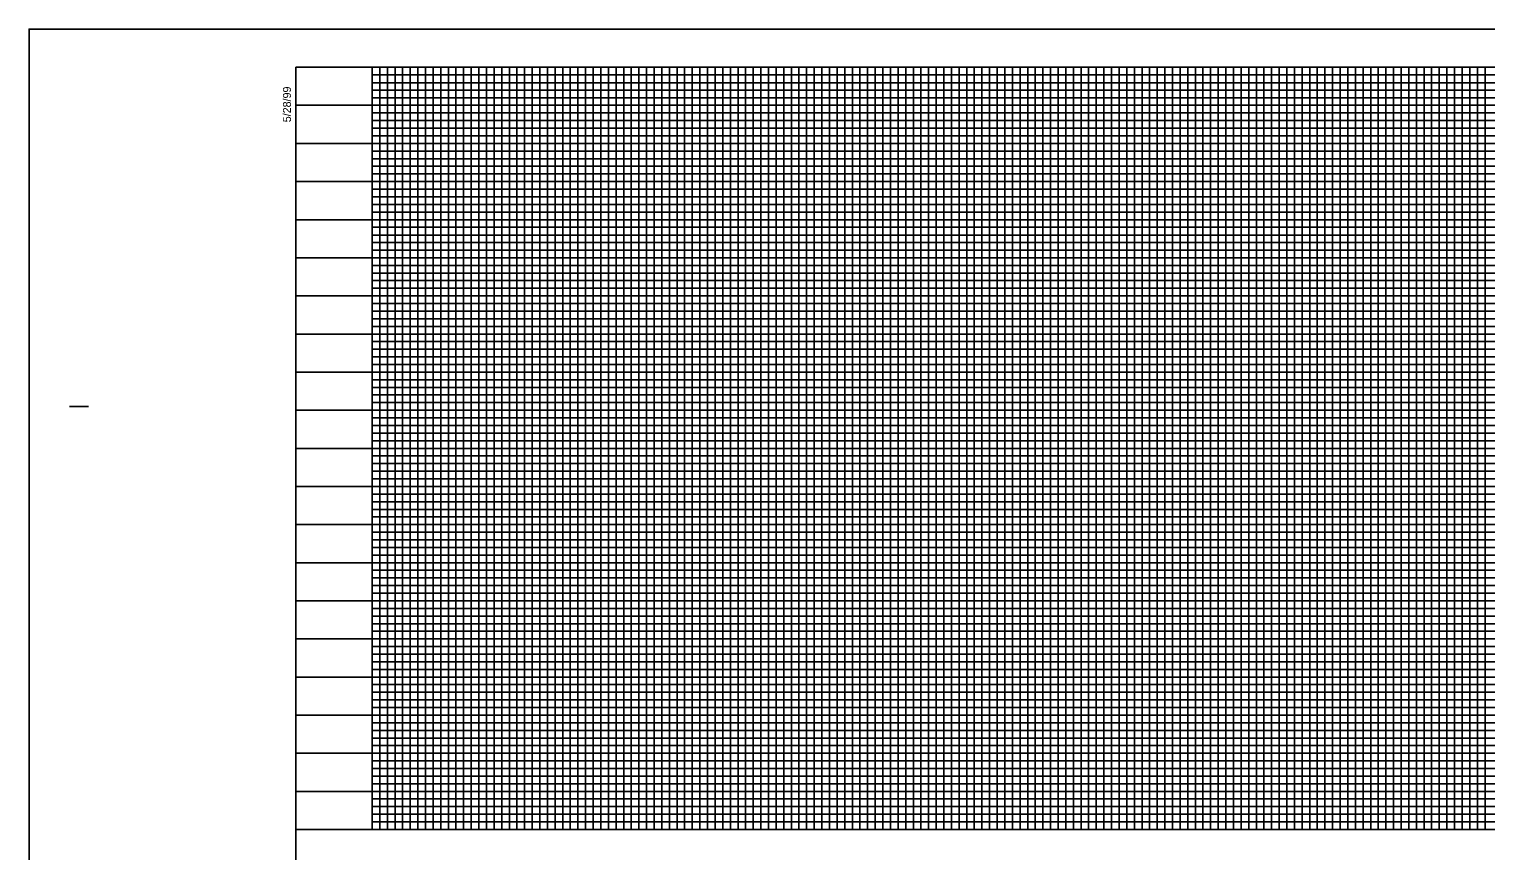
# Model space of a CAD drawing. Extents: x 573078 to 573116.9, y -55221.3 to -55199.3.
# Drawn here: x 573078.01 to 573097.13, y -55210.08 to -55199.3 of the extents above; entities that cross this region are included whole.
import ezdxf

# ---------------------------------------------------------------- set-up
doc = ezdxf.new("R2010")
doc.units = 0
for name, color, linetype in [('Sheet Clip Boundary CELL', 7, 'Continuous'), ('Sheet Plot Border Inside CELL', 7, 'Continuous'), ('Sheet Profile CELL', 7, 'Continuous'), ('Sheet Profile Grid Major CELL', 7, 'Continuous'), ('Sheet Profile Grid Middle CELL', 7, 'Continuous'), ('Sheet Profile Grid Minor CELL', 7, 'Continuous')]:
    doc.layers.add(name, color=color, linetype=linetype)

msp = doc.modelspace()

# ---------------------------------------------------------------- linework, layer by layer
at = {"layer": 'Sheet Clip Boundary CELL'}
msp.add_lwpolyline([(573082.514, -55199.798), (573107.514, -55199.798), (573107.514, -55204.798), (573110.514, -55204.798), (573110.514, -55209.798), (573082.514, -55209.798)], close=True, dxfattribs=at)
at = {"layer": 'Sheet Plot Border Inside CELL'}
msp.add_lwpolyline([(573112.014, -55199.298), (573078.014, -55199.298), (573078.014, -55221.298), (573112.014, -55221.298)], close=True, dxfattribs=at)
at = {"layer": 'Sheet Profile CELL'}
for p, q in [((573078.544, -55204.248), (573078.794, -55204.248)), ((573081.514, -55209.798), (573111.514, -55209.798))]:
    msp.add_line(p, q, dxfattribs=at)
msp.add_lwpolyline([(573111.514, -55199.798), (573081.514, -55199.798), (573081.514, -55220.798), (573111.514, -55220.798)], close=True, dxfattribs=at)
at = {"layer": 'Sheet Profile Grid Major CELL'}
for points in [[(573082.514, -55199.798), (573082.514, -55209.798), (573083.514, -55209.798), (573083.514, -55199.798), (573084.514, -55199.798), (573084.514, -55209.798), (573085.514, -55209.798), (573085.514, -55199.798), (573086.514, -55199.798), (573086.514, -55209.798), (573087.514, -55209.798), (573087.514, -55199.798), (573088.514, -55199.798), (573088.514, -55209.798), (573089.514, -55209.798), (573089.514, -55199.798), (573090.514, -55199.798), (573090.514, -55209.798), (573091.514, -55209.798), (573091.514, -55199.798), (573092.514, -55199.798), (573092.514, -55209.798), (573093.514, -55209.798), (573093.514, -55199.798), (573094.514, -55199.798), (573094.514, -55209.798), (573095.514, -55209.798), (573095.514, -55199.798), (573096.514, -55199.798), (573096.514, -55209.798), (573097.514, -55209.798)], [(573081.514, -55200.798), (573107.514, -55200.798)], [(573107.514, -55201.798), (573081.514, -55201.798), (573081.514, -55202.798), (573107.514, -55202.798)], [(573107.514, -55203.798), (573081.514, -55203.798), (573081.514, -55204.798), (573111.514, -55204.798)], [(573111.514, -55205.798), (573081.514, -55205.798), (573081.514, -55206.798), (573111.514, -55206.798)], [(573111.514, -55207.798), (573081.514, -55207.798), (573081.514, -55207.798), (573081.514, -55208.798), (573111.514, -55208.798)]]:
    msp.add_lwpolyline(points, dxfattribs=at)
at = {"layer": 'Sheet Profile Grid Middle CELL'}
msp.add_line((573081.514, -55200.298), (573107.514, -55200.298), dxfattribs=at)
for points in [[(573083.014, -55199.798), (573083.014, -55209.798), (573084.014, -55209.798), (573084.014, -55199.798), (573085.014, -55199.798), (573085.014, -55209.798), (573086.014, -55209.798), (573086.014, -55199.798), (573087.014, -55199.798), (573087.014, -55209.798), (573088.014, -55209.798), (573088.014, -55199.798), (573089.014, -55199.798), (573089.014, -55209.798), (573090.014, -55209.798), (573090.014, -55199.798), (573091.014, -55199.798), (573091.014, -55209.798), (573092.014, -55209.798), (573092.014, -55199.798), (573093.014, -55199.798), (573093.014, -55209.798), (573094.014, -55209.798), (573094.014, -55209.798), (573094.014, -55199.798), (573095.014, -55199.798), (573095.014, -55209.798), (573096.014, -55209.798), (573096.014, -55199.798), (573097.014, -55199.798), (573097.014, -55209.798), (573098.014, -55209.798)], [(573107.514, -55201.298), (573081.514, -55201.298), (573081.514, -55202.298), (573107.514, -55202.298)], [(573107.514, -55203.298), (573081.514, -55203.298), (573081.514, -55204.298), (573107.514, -55204.298)], [(573111.514, -55205.298), (573081.514, -55205.298), (573081.514, -55206.298), (573111.514, -55206.298)], [(573111.514, -55207.298), (573081.514, -55207.298), (573081.514, -55208.298), (573111.514, -55208.298)], [(573111.514, -55209.298), (573081.514, -55209.298)]]:
    msp.add_lwpolyline(points, dxfattribs=at)
at = {"layer": 'Sheet Profile Grid Minor CELL'}
for p, q in [((573082.514, -55199.898), (573107.514, -55199.898)), ((573082.514, -55199.998), (573082.514, -55199.998)), ((573107.514, -55199.998), (573082.514, -55200.005)), ((573082.514, -55200.098), (573107.514, -55200.098)), ((573107.514, -55202.498), (573082.514, -55202.498)), ((573107.514, -55202.598), (573082.514, -55202.598)), ((573107.514, -55202.698), (573082.514, -55202.698)), ((573082.514, -55202.898), (573107.514, -55202.898)), ((573107.514, -55202.998), (573082.514, -55202.998)), ((573082.514, -55203.098), (573107.514, -55203.098)), ((573107.514, -55203.498), (573082.514, -55203.498)), ((573082.514, -55203.598), (573107.514, -55203.598)), ((573107.514, -55203.998), (573082.514, -55203.998)), ((573082.514, -55204.098), (573107.514, -55204.098)), ((573107.514, -55204.498), (573082.514, -55204.498)), ((573082.514, -55204.598), (573107.514, -55204.598)), ((573107.514, -55204.698), (573082.514, -55204.698)), ((573082.514, -55204.898), (573110.514, -55204.898)), ((573110.514, -55204.998), (573082.514, -55204.998)), ((573082.514, -55205.098), (573110.514, -55205.098)), ((573110.514, -55205.198), (573082.514, -55205.198)), ((573082.514, -55205.398), (573110.514, -55205.398)), ((573110.514, -55205.498), (573082.514, -55205.498)), ((573082.514, -55205.598), (573110.514, -55205.598)), ((573110.514, -55205.698), (573082.514, -55205.698)), ((573082.514, -55205.898), (573110.514, -55205.898)), ((573110.514, -55205.998), (573082.514, -55205.998)), ((573082.514, -55206.098), (573110.514, -55206.098)), ((573110.514, -55206.198), (573082.514, -55206.198)), ((573082.514, -55206.398), (573110.514, -55206.398)), ((573110.514, -55206.498), (573082.514, -55206.498)), ((573082.514, -55206.598), (573110.514, -55206.598)), ((573110.514, -55206.698), (573082.514, -55206.698)), ((573082.514, -55206.898), (573110.514, -55206.898)), ((573110.514, -55206.998), (573082.514, -55206.998)), ((573082.514, -55207.098), (573110.514, -55207.098)), ((573110.514, -55207.198), (573082.514, -55207.198)), ((573082.514, -55207.398), (573110.514, -55207.398)), ((573110.514, -55207.498), (573082.514, -55207.498)), ((573110.514, -55207.598), (573082.514, -55207.598)), ((573110.514, -55207.698), (573082.514, -55207.698)), ((573082.514, -55207.898), (573110.514, -55207.898)), ((573110.514, -55207.998), (573082.514, -55207.998)), ((573082.514, -55208.098), (573110.514, -55208.098)), ((573110.514, -55208.198), (573082.514, -55208.198)), ((573082.514, -55208.398), (573110.514, -55208.398)), ((573110.514, -55208.498), (573082.514, -55208.498)), ((573082.514, -55208.598), (573110.514, -55208.598)), ((573110.514, -55208.698), (573082.514, -55208.698)), ((573082.514, -55208.898), (573110.514, -55208.898)), ((573110.514, -55208.998), (573082.514, -55208.998)), ((573082.514, -55209.098), (573110.514, -55209.098)), ((573110.514, -55209.198), (573082.514, -55209.198)), ((573082.514, -55209.398), (573110.514, -55209.398)), ((573110.514, -55209.498), (573082.514, -55209.498)), ((573082.514, -55209.598), (573110.514, -55209.598))]:
    msp.add_line(p, q, dxfattribs=at)
for points in [[(573082.614, -55199.798), (573082.614, -55209.798), (573082.714, -55209.798), (573082.714, -55199.798), (573082.814, -55199.798), (573082.814, -55209.798), (573082.914, -55209.798), (573082.914, -55199.798), (573083.114, -55199.798), (573083.114, -55209.798), (573083.214, -55209.798), (573083.214, -55199.798), (573083.314, -55199.798), (573083.314, -55209.798), (573083.414, -55209.798), (573083.614, -55209.798), (573083.714, -55209.798), (573083.714, -55199.798), (573083.814, -55199.798), (573083.814, -55209.798), (573083.914, -55209.798), (573083.914, -55199.798), (573084.114, -55199.798), (573084.114, -55209.798), (573084.214, -55209.798), (573084.214, -55199.798), (573084.314, -55199.798), (573084.314, -55209.798), (573084.414, -55209.798), (573084.414, -55199.798), (573084.614, -55199.798), (573084.614, -55209.798), (573084.714, -55209.798), (573084.714, -55199.798), (573084.814, -55199.798), (573084.814, -55209.798), (573084.914, -55209.798), (573084.914, -55199.798), (573085.114, -55199.798), (573085.114, -55209.798), (573085.214, -55209.798), (573085.214, -55199.798), (573085.314, -55199.798), (573085.314, -55209.798), (573085.414, -55209.798), (573085.414, -55199.798), (573085.614, -55199.798), (573085.614, -55209.798), (573085.714, -55209.798), (573085.714, -55199.798), (573085.814, -55199.798), (573085.814, -55209.798), (573085.914, -55209.798), (573085.914, -55199.798), (573086.114, -55199.798), (573086.114, -55209.798), (573086.214, -55209.798), (573086.214, -55199.798), (573086.314, -55199.798), (573086.314, -55209.798), (573086.414, -55209.798), (573086.414, -55199.798), (573086.614, -55199.798), (573086.614, -55209.798), (573086.714, -55209.798), (573086.714, -55199.798), (573086.814, -55199.798), (573086.814, -55209.798)], [(573083.414, -55209.798), (573083.414, -55199.798), (573083.614, -55199.798), (573083.614, -55209.798)], [(573086.814, -55209.798), (573086.914, -55209.798), (573086.914, -55199.798), (573087.114, -55199.798), (573087.114, -55209.798), (573087.214, -55209.798), (573087.214, -55199.798), (573087.314, -55199.798), (573087.314, -55209.798), (573087.414, -55209.798), (573087.414, -55199.798), (573087.614, -55199.798), (573087.614, -55209.798), (573087.714, -55209.798), (573087.714, -55199.798), (573087.814, -55199.798), (573087.814, -55209.798), (573087.914, -55209.798), (573087.914, -55199.798), (573088.114, -55199.798), (573088.114, -55209.798), (573088.214, -55209.798), (573088.214, -55199.798), (573088.314, -55199.798), (573088.314, -55209.798), (573088.414, -55209.798), (573088.414, -55199.798), (573088.614, -55199.798), (573088.614, -55209.798), (573088.714, -55209.798), (573088.714, -55199.798), (573088.814, -55199.798), (573088.814, -55209.798), (573088.914, -55209.798), (573088.914, -55199.798), (573089.114, -55199.798), (573089.114, -55209.798), (573089.214, -55209.798), (573089.214, -55199.798), (573089.314, -55199.798), (573089.314, -55209.798), (573089.414, -55209.798), (573089.414, -55199.798), (573089.614, -55199.798), (573089.614, -55209.798), (573089.714, -55209.798), (573089.714, -55199.798), (573089.814, -55199.798), (573089.814, -55209.798), (573089.914, -55209.798), (573089.914, -55199.798), (573090.114, -55199.798), (573090.114, -55209.798), (573090.214, -55209.798), (573090.214, -55199.798), (573090.314, -55199.798), (573090.314, -55209.798), (573090.414, -55209.798), (573090.414, -55199.798), (573090.614, -55199.798), (573090.614, -55209.798), (573090.714, -55209.798), (573090.714, -55199.798), (573090.814, -55199.798), (573090.814, -55209.798), (573090.914, -55209.798), (573090.914, -55199.798), (573091.114, -55199.798), (573091.114, -55209.798), (573091.214, -55209.798), (573091.214, -55199.798), (573091.314, -55199.798), (573091.314, -55209.798), (573091.414, -55209.798), (573091.414, -55199.798), (573091.614, -55199.798), (573091.614, -55209.798), (573091.714, -55209.798), (573091.714, -55199.798), (573091.814, -55199.798), (573091.814, -55209.798), (573091.914, -55209.798), (573091.914, -55199.798), (573092.114, -55199.798), (573092.114, -55209.798), (573092.214, -55209.798), (573092.214, -55199.798), (573092.314, -55199.798), (573092.314, -55209.798), (573092.414, -55209.798), (573092.414, -55199.798), (573092.614, -55199.798), (573092.614, -55209.798), (573092.714, -55209.798), (573092.714, -55199.798), (573092.814, -55199.798), (573092.814, -55209.798), (573092.914, -55209.798), (573092.914, -55199.798), (573093.114, -55199.798)], [(573093.114, -55199.798), (573093.114, -55209.798), (573093.214, -55209.798), (573093.214, -55199.798), (573093.314, -55199.798), (573093.314, -55209.798), (573093.414, -55209.798), (573093.414, -55199.798), (573093.614, -55199.798), (573093.614, -55209.798), (573093.714, -55209.798), (573093.714, -55199.798), (573093.814, -55199.798), (573093.814, -55209.798), (573093.914, -55209.798), (573093.914, -55199.798), (573094.114, -55199.798), (573094.114, -55209.798), (573094.214, -55209.798), (573094.214, -55199.798), (573094.314, -55199.798), (573094.314, -55209.798), (573094.414, -55209.798), (573094.414, -55199.798), (573094.614, -55199.798), (573094.614, -55209.798), (573094.714, -55209.798), (573094.714, -55199.798), (573094.814, -55199.798), (573094.814, -55209.798), (573094.914, -55209.798), (573094.914, -55199.798), (573095.114, -55199.798), (573095.114, -55209.798), (573095.214, -55209.798), (573095.214, -55199.798), (573095.314, -55199.798), (573095.314, -55209.798), (573095.414, -55209.798), (573095.414, -55199.798), (573095.614, -55199.798), (573095.614, -55209.798), (573095.614, -55209.798), (573095.714, -55209.798), (573095.714, -55199.798), (573095.814, -55199.798), (573095.814, -55209.798), (573095.914, -55209.798), (573095.914, -55199.798), (573096.114, -55199.798), (573096.114, -55209.798), (573096.214, -55209.798), (573096.214, -55199.798), (573096.314, -55199.798), (573096.314, -55209.798), (573096.414, -55209.798), (573096.414, -55199.798), (573096.614, -55199.798), (573096.614, -55209.798), (573096.714, -55209.798), (573096.714, -55199.798), (573096.814, -55199.798), (573096.814, -55209.798), (573096.914, -55209.798), (573096.914, -55199.798), (573097.114, -55199.798), (573097.114, -55209.798), (573097.214, -55209.798)], [(573107.514, -55200.198), (573082.514, -55200.198), (573082.514, -55200.398), (573107.514, -55200.398)], [(573107.514, -55200.498), (573082.514, -55200.498), (573082.514, -55200.598), (573107.514, -55200.598)], [(573107.514, -55200.698), (573082.514, -55200.698), (573082.514, -55200.898), (573107.514, -55200.898)], [(573107.514, -55200.998), (573082.514, -55200.998), (573082.514, -55201.098), (573107.514, -55201.098)], [(573107.514, -55201.198), (573082.514, -55201.198), (573082.514, -55201.398), (573107.514, -55201.398)], [(573107.514, -55201.498), (573082.514, -55201.498), (573082.514, -55201.598), (573107.514, -55201.598)], [(573107.514, -55201.698), (573082.514, -55201.698), (573082.514, -55201.898), (573107.514, -55201.898)], [(573107.514, -55202), (573082.516, -55202), (573082.516, -55202.098), (573107.514, -55202.098)], [(573107.514, -55202.198), (573082.514, -55202.198), (573082.514, -55202.398), (573107.514, -55202.398)], [(573107.514, -55203.198), (573082.514, -55203.198), (573082.514, -55203.398), (573107.514, -55203.398)], [(573107.514, -55203.698), (573082.514, -55203.698), (573082.514, -55203.898), (573107.514, -55203.898)], [(573107.514, -55204.198), (573082.514, -55204.198), (573082.514, -55204.398), (573107.514, -55204.398)], [(573110.514, -55209.698), (573082.514, -55209.698)]]:
    msp.add_lwpolyline(points, dxfattribs=at)

# ---------------------------------------------------------------- texts
at = {"layer": 'Sheet Profile CELL'}
msp.add_text('5/28/99', height=0.105, rotation=90, dxfattribs=at).set_placement((573081.449, -55200.52))

doc.saveas('drawing.dxf')
